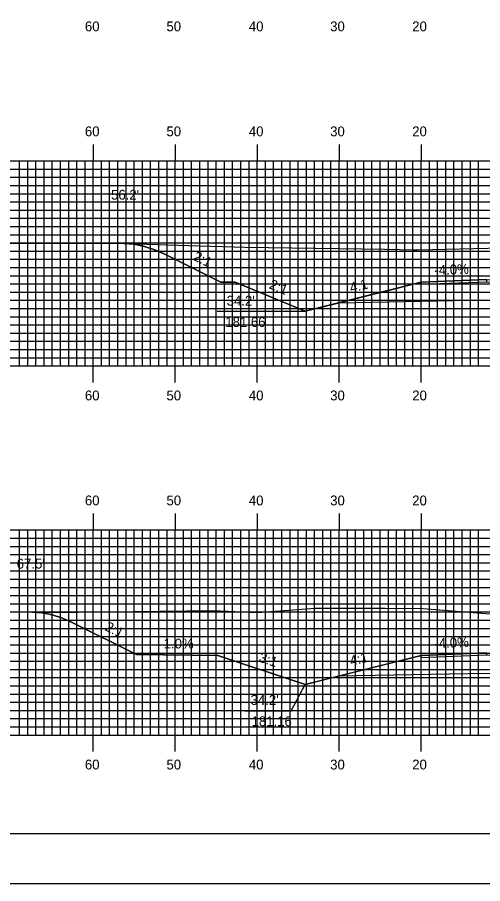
# Model space of a CAD drawing. Extents: x 1797601 to 1797944, y 442591 to 442811.
# Drawn here: x 1797697.2 to 1797753.9, y 442590.5 to 442696.2 of the extents above; entities that cross this region are included whole.
import ezdxf

# ---------------------------------------------------------------- set-up
doc = ezdxf.new("R2010")
doc.units = 0
for name, color, linetype in [('ANNOTATION', 7, 'Continuous'), ('BORDER', 7, 'Continuous'), ('D_Roadway_Centerline', 7, 'Continuous'), ('D_Roadway_Edge_Shoulder', 7, 'Continuous'), ('D_Roadway_SlopeLines', 7, 'Continuous'), ('D_Roadway_SubGrade', 7, 'Continuous'), ('D_Text_Standard', 7, 'Continuous'), ('H_V ANNOTATION', 7, 'Continuous'), ('MAJOR', 7, 'Continuous'), ('MINOR', 7, 'Continuous'), ('PDRAIN', 7, 'Continuous'), ('PLOT BOUNDARY', 7, 'Continuous'), ('S_Roadway_Centerline', 7, 'Continuous')]:
    doc.layers.add(name, color=color, linetype=linetype)

msp = doc.modelspace()

# ---------------------------------------------------------------- linework, layer by layer
at = {"layer": 'ANNOTATION'}
msp.add_lwpolyline([(1797724.9, 442611.62), (1797730.59, 442611.62), (1797732.27, 442614.83)], dxfattribs=at)
at = {"layer": 'BORDER'}
msp.add_lwpolyline([(1797616.84, 442596.67), (1797936.84, 442596.67), (1797936.84, 442806.67), (1797616.84, 442806.67)], close=True, dxfattribs=at)
at = {"layer": 'D_Roadway_Centerline'}
for points in [[(1797710.19, 442668.6), (1797711.44, 442668.5), (1797712.69, 442668.24), (1797713.94, 442667.84), (1797715.19, 442667.28), (1797721.99, 442663.89), (1797723.77, 442663.87), (1797732.27, 442660.33), (1797736.27, 442661.33), (1797746.44, 442663.87), (1797754.44, 442664.19), (1797766.44, 442663.95), (1797778.44, 442663.71), (1797786.44, 442663.39), (1797796.62, 442660.85), (1797800.62, 442659.85), (1797809.12, 442663.39), (1797813.34, 442663.43), (1797817.69, 442665.61), (1797818.94, 442666.15), (1797820.19, 442666.52), (1797821.44, 442666.73), (1797822.69, 442666.77)], [(1797698.94, 442623.65), (1797700.19, 442623.55), (1797701.44, 442623.31), (1797702.69, 442622.91), (1797703.94, 442622.36), (1797711.73, 442618.47), (1797721.64, 442618.37), (1797732.27, 442614.83), (1797736.27, 442615.83), (1797746.44, 442618.37), (1797754.44, 442618.69), (1797766.44, 442618.45), (1797778.44, 442618.21), (1797786.44, 442617.89), (1797796.62, 442615.35), (1797800.62, 442614.35), (1797811.25, 442617.89), (1797823.86, 442618.01), (1797828.94, 442620.56), (1797830.19, 442621.1), (1797831.44, 442621.48), (1797832.69, 442621.7), (1797833.94, 442621.75)]]:
    msp.add_lwpolyline(points, dxfattribs=at)
at = {"layer": 'D_Roadway_Edge_Shoulder'}
for points in [[(1797754.44, 442664.19), (1797746.44, 442663.87), (1797746.44, 442663.62), (1797754.44, 442663.94)], [(1797754.44, 442618.69), (1797746.44, 442618.37), (1797746.44, 442618.12), (1797754.44, 442618.44)]]:
    msp.add_lwpolyline(points, close=True, dxfattribs=at)
at = {"layer": 'D_Roadway_SlopeLines'}
for points in [[(1797723.77, 442663.87), (1797721.99, 442663.89), (1797715.19, 442667.28), (1797713.94, 442667.84), (1797712.69, 442668.24), (1797711.44, 442668.5), (1797710.19, 442668.6)], [(1797732.27, 442660.33), (1797723.77, 442663.87)], [(1797746.44, 442663.87), (1797732.27, 442660.33)], [(1797721.64, 442618.37), (1797711.73, 442618.47), (1797703.94, 442622.36), (1797702.69, 442622.91), (1797701.44, 442623.31), (1797700.19, 442623.55), (1797698.94, 442623.65)], [(1797732.27, 442614.83), (1797721.64, 442618.37)], [(1797746.44, 442618.37), (1797732.27, 442614.83)]]:
    msp.add_lwpolyline(points, dxfattribs=at)
at = {"layer": 'D_Roadway_SubGrade'}
for points in [[(1797754.44, 442661.69), (1797736.27, 442661.33), (1797746.44, 442663.87), (1797746.44, 442663.62), (1797754.44, 442663.94), (1797766.44, 442663.7), (1797778.44, 442663.46), (1797786.44, 442663.14), (1797786.44, 442663.39), (1797796.62, 442660.85), (1797778.44, 442661.21), (1797766.44, 442661.45)], [(1797754.44, 442616.19), (1797736.27, 442615.83), (1797746.44, 442618.37), (1797746.44, 442618.12), (1797754.44, 442618.44), (1797766.44, 442618.2), (1797778.44, 442617.96), (1797786.44, 442617.64), (1797786.44, 442617.89), (1797796.62, 442615.35), (1797778.44, 442615.71), (1797766.44, 442615.95)]]:
    msp.add_lwpolyline(points, close=True, dxfattribs=at)
at = {"layer": 'MAJOR'}
for p, q in [((1797706.44, 442680.67), (1797706.44, 442678.67)), ((1797716.44, 442680.67), (1797716.44, 442678.67)), ((1797726.44, 442680.67), (1797726.44, 442678.67)), ((1797736.44, 442680.67), (1797736.44, 442678.67)), ((1797746.44, 442680.67), (1797746.44, 442678.67)), ((1797626.44, 442678.67), (1797906.44, 442678.67)), ((1797626.44, 442678.67), (1797906.44, 442678.67)), ((1797706.44, 442653.67), (1797706.44, 442678.67)), ((1797716.44, 442653.67), (1797716.44, 442678.67)), ((1797726.44, 442653.67), (1797726.44, 442678.67)), ((1797736.44, 442653.67), (1797736.44, 442678.67)), ((1797746.44, 442653.67), (1797746.44, 442678.67)), ((1797626.44, 442673.67), (1797906.44, 442673.67)), ((1797626.44, 442668.67), (1797906.44, 442668.67)), ((1797626.44, 442663.67), (1797906.44, 442663.67)), ((1797626.44, 442658.67), (1797906.44, 442658.67)), ((1797626.44, 442653.67), (1797906.44, 442653.67)), ((1797626.44, 442653.67), (1797906.44, 442653.67)), ((1797706.44, 442651.66), (1797706.44, 442653.67)), ((1797716.44, 442651.66), (1797716.44, 442653.67)), ((1797726.44, 442651.66), (1797726.44, 442653.67)), ((1797736.44, 442651.66), (1797736.44, 442653.67)), ((1797746.44, 442651.66), (1797746.44, 442653.67)), ((1797706.44, 442635.67), (1797706.44, 442633.67)), ((1797716.44, 442635.67), (1797716.44, 442633.67)), ((1797726.44, 442635.67), (1797726.44, 442633.67)), ((1797736.44, 442635.67), (1797736.44, 442633.67)), ((1797746.44, 442635.67), (1797746.44, 442633.67)), ((1797626.44, 442633.67), (1797906.44, 442633.67)), ((1797626.44, 442633.67), (1797906.44, 442633.67)), ((1797706.44, 442608.67), (1797706.44, 442633.67)), ((1797716.44, 442608.67), (1797716.44, 442633.67)), ((1797726.44, 442608.67), (1797726.44, 442633.67)), ((1797736.44, 442608.67), (1797736.44, 442633.67)), ((1797746.44, 442608.67), (1797746.44, 442633.67)), ((1797626.44, 442628.67), (1797906.44, 442628.67)), ((1797626.44, 442623.67), (1797906.44, 442623.67)), ((1797626.44, 442618.67), (1797906.44, 442618.67)), ((1797626.44, 442613.67), (1797906.44, 442613.67)), ((1797626.44, 442608.67), (1797906.44, 442608.67)), ((1797626.44, 442608.67), (1797906.44, 442608.67)), ((1797706.44, 442606.66), (1797706.44, 442608.67)), ((1797716.44, 442606.66), (1797716.44, 442608.67)), ((1797726.44, 442606.66), (1797726.44, 442608.67)), ((1797736.44, 442606.66), (1797736.44, 442608.67)), ((1797746.44, 442606.66), (1797746.44, 442608.67))]:
    msp.add_line(p, q, dxfattribs=at)
at = {"layer": 'MINOR'}
for p, q in [((1797697.44, 442653.67), (1797697.44, 442678.67)), ((1797698.44, 442653.67), (1797698.44, 442678.67)), ((1797699.44, 442653.67), (1797699.44, 442678.67)), ((1797700.44, 442653.67), (1797700.44, 442678.67)), ((1797701.44, 442653.67), (1797701.44, 442678.67)), ((1797702.44, 442653.67), (1797702.44, 442678.67)), ((1797703.44, 442653.67), (1797703.44, 442678.67)), ((1797704.44, 442653.67), (1797704.44, 442678.67)), ((1797705.44, 442653.67), (1797705.44, 442678.67)), ((1797707.44, 442653.67), (1797707.44, 442678.67)), ((1797708.44, 442653.67), (1797708.44, 442678.67)), ((1797709.44, 442653.67), (1797709.44, 442678.67)), ((1797710.44, 442653.67), (1797710.44, 442678.67)), ((1797711.44, 442653.67), (1797711.44, 442678.67)), ((1797712.44, 442653.67), (1797712.44, 442678.67)), ((1797713.44, 442653.67), (1797713.44, 442678.67)), ((1797714.44, 442653.67), (1797714.44, 442678.67)), ((1797715.44, 442653.67), (1797715.44, 442678.67)), ((1797717.44, 442653.67), (1797717.44, 442678.67)), ((1797718.44, 442653.67), (1797718.44, 442678.67)), ((1797719.44, 442653.67), (1797719.44, 442678.67)), ((1797720.44, 442653.67), (1797720.44, 442678.67)), ((1797721.44, 442653.67), (1797721.44, 442678.67)), ((1797722.44, 442653.67), (1797722.44, 442678.67)), ((1797723.44, 442653.67), (1797723.44, 442678.67)), ((1797724.44, 442653.67), (1797724.44, 442678.67)), ((1797725.44, 442653.67), (1797725.44, 442678.67)), ((1797727.44, 442653.67), (1797727.44, 442678.67)), ((1797728.44, 442653.67), (1797728.44, 442678.67)), ((1797729.44, 442653.67), (1797729.44, 442678.67)), ((1797730.44, 442653.67), (1797730.44, 442678.67)), ((1797731.44, 442653.67), (1797731.44, 442678.67)), ((1797732.44, 442653.67), (1797732.44, 442678.67)), ((1797733.44, 442653.67), (1797733.44, 442678.67)), ((1797734.44, 442653.67), (1797734.44, 442678.67)), ((1797735.44, 442653.67), (1797735.44, 442678.67)), ((1797737.44, 442653.67), (1797737.44, 442678.67)), ((1797738.44, 442653.67), (1797738.44, 442678.67)), ((1797739.44, 442653.67), (1797739.44, 442678.67)), ((1797740.44, 442653.67), (1797740.44, 442678.67)), ((1797741.44, 442653.67), (1797741.44, 442678.67)), ((1797742.44, 442653.67), (1797742.44, 442678.67)), ((1797743.44, 442653.67), (1797743.44, 442678.67)), ((1797744.44, 442653.67), (1797744.44, 442678.67)), ((1797745.44, 442653.67), (1797745.44, 442678.67)), ((1797747.44, 442653.67), (1797747.44, 442678.67)), ((1797748.44, 442653.67), (1797748.44, 442678.67)), ((1797749.44, 442653.67), (1797749.44, 442678.67)), ((1797750.44, 442653.67), (1797750.44, 442678.67)), ((1797751.44, 442653.67), (1797751.44, 442678.67)), ((1797752.44, 442653.67), (1797752.44, 442678.67)), ((1797753.44, 442653.67), (1797753.44, 442678.67)), ((1797626.44, 442677.67), (1797906.44, 442677.67)), ((1797626.44, 442676.67), (1797906.44, 442676.67)), ((1797626.44, 442675.67), (1797906.44, 442675.67)), ((1797626.44, 442674.67), (1797906.44, 442674.67)), ((1797626.44, 442672.67), (1797906.44, 442672.67)), ((1797626.44, 442671.67), (1797906.44, 442671.67)), ((1797626.44, 442670.67), (1797906.44, 442670.67)), ((1797626.44, 442669.67), (1797906.44, 442669.67)), ((1797626.44, 442667.67), (1797906.44, 442667.67)), ((1797626.44, 442666.67), (1797906.44, 442666.67)), ((1797626.44, 442665.67), (1797906.44, 442665.67)), ((1797626.44, 442664.67), (1797906.44, 442664.67)), ((1797626.44, 442662.67), (1797906.44, 442662.67)), ((1797626.44, 442661.67), (1797906.44, 442661.67)), ((1797626.44, 442660.67), (1797906.44, 442660.67)), ((1797626.44, 442659.67), (1797906.44, 442659.67)), ((1797626.44, 442657.67), (1797906.44, 442657.67)), ((1797626.44, 442656.67), (1797906.44, 442656.67)), ((1797626.44, 442655.67), (1797906.44, 442655.67)), ((1797626.44, 442654.67), (1797906.44, 442654.67)), ((1797697.44, 442608.67), (1797697.44, 442633.67)), ((1797698.44, 442608.67), (1797698.44, 442633.67)), ((1797699.44, 442608.67), (1797699.44, 442633.67)), ((1797700.44, 442608.67), (1797700.44, 442633.67)), ((1797701.44, 442608.67), (1797701.44, 442633.67)), ((1797702.44, 442608.67), (1797702.44, 442633.67)), ((1797703.44, 442608.67), (1797703.44, 442633.67)), ((1797704.44, 442608.67), (1797704.44, 442633.67)), ((1797705.44, 442608.67), (1797705.44, 442633.67)), ((1797707.44, 442608.67), (1797707.44, 442633.67)), ((1797708.44, 442608.67), (1797708.44, 442633.67)), ((1797709.44, 442608.67), (1797709.44, 442633.67)), ((1797710.44, 442608.67), (1797710.44, 442633.67)), ((1797711.44, 442608.67), (1797711.44, 442633.67)), ((1797712.44, 442608.67), (1797712.44, 442633.67)), ((1797713.44, 442608.67), (1797713.44, 442633.67)), ((1797714.44, 442608.67), (1797714.44, 442633.67)), ((1797715.44, 442608.67), (1797715.44, 442633.67)), ((1797717.44, 442608.67), (1797717.44, 442633.67)), ((1797718.44, 442608.67), (1797718.44, 442633.67)), ((1797719.44, 442608.67), (1797719.44, 442633.67)), ((1797720.44, 442608.67), (1797720.44, 442633.67)), ((1797721.44, 442608.67), (1797721.44, 442633.67)), ((1797722.44, 442608.67), (1797722.44, 442633.67)), ((1797723.44, 442608.67), (1797723.44, 442633.67)), ((1797724.44, 442608.67), (1797724.44, 442633.67)), ((1797725.44, 442608.67), (1797725.44, 442633.67)), ((1797727.44, 442608.67), (1797727.44, 442633.67)), ((1797728.44, 442608.67), (1797728.44, 442633.67)), ((1797729.44, 442608.67), (1797729.44, 442633.67)), ((1797730.44, 442608.67), (1797730.44, 442633.67)), ((1797731.44, 442608.67), (1797731.44, 442633.67)), ((1797732.44, 442608.67), (1797732.44, 442633.67)), ((1797733.44, 442608.67), (1797733.44, 442633.67)), ((1797734.44, 442608.67), (1797734.44, 442633.67)), ((1797735.44, 442608.67), (1797735.44, 442633.67)), ((1797737.44, 442608.67), (1797737.44, 442633.67)), ((1797738.44, 442608.67), (1797738.44, 442633.67)), ((1797739.44, 442608.67), (1797739.44, 442633.67)), ((1797740.44, 442608.67), (1797740.44, 442633.67)), ((1797741.44, 442608.67), (1797741.44, 442633.67)), ((1797742.44, 442608.67), (1797742.44, 442633.67)), ((1797743.44, 442608.67), (1797743.44, 442633.67)), ((1797744.44, 442608.67), (1797744.44, 442633.67)), ((1797745.44, 442608.67), (1797745.44, 442633.67)), ((1797747.44, 442608.67), (1797747.44, 442633.67)), ((1797748.44, 442608.67), (1797748.44, 442633.67)), ((1797749.44, 442608.67), (1797749.44, 442633.67)), ((1797750.44, 442608.67), (1797750.44, 442633.67)), ((1797751.44, 442608.67), (1797751.44, 442633.67)), ((1797752.44, 442608.67), (1797752.44, 442633.67)), ((1797753.44, 442608.67), (1797753.44, 442633.67)), ((1797626.44, 442632.67), (1797906.44, 442632.67)), ((1797626.44, 442631.67), (1797906.44, 442631.67)), ((1797626.44, 442630.67), (1797906.44, 442630.67)), ((1797626.44, 442629.67), (1797906.44, 442629.67)), ((1797626.44, 442627.67), (1797906.44, 442627.67)), ((1797626.44, 442626.67), (1797906.44, 442626.67)), ((1797626.44, 442625.67), (1797906.44, 442625.67)), ((1797626.44, 442624.67), (1797906.44, 442624.67)), ((1797626.44, 442622.67), (1797906.44, 442622.67)), ((1797626.44, 442621.67), (1797906.44, 442621.67)), ((1797626.44, 442620.67), (1797906.44, 442620.67)), ((1797626.44, 442619.67), (1797906.44, 442619.67)), ((1797626.44, 442617.67), (1797906.44, 442617.67)), ((1797626.44, 442616.67), (1797906.44, 442616.67)), ((1797626.44, 442615.67), (1797906.44, 442615.67)), ((1797626.44, 442614.67), (1797906.44, 442614.67)), ((1797626.44, 442612.67), (1797906.44, 442612.67)), ((1797626.44, 442611.67), (1797906.44, 442611.67)), ((1797626.44, 442610.67), (1797906.44, 442610.67)), ((1797626.44, 442609.67), (1797906.44, 442609.67))]:
    msp.add_line(p, q, dxfattribs=at)
at = {"layer": 'PDRAIN'}
msp.add_line((1797721.55, 442660.33), (1797732.27, 442660.33), dxfattribs=at)
at = {"layer": 'PLOT BOUNDARY'}
msp.add_lwpolyline([(1797600.66, 442590.55), (1797940.66, 442590.55), (1797940.66, 442810.55), (1797600.66, 442810.55)], close=True, dxfattribs=at)
at = {"layer": 'S_Roadway_Centerline'}
for points in [[(1797692.6, 442668.6), (1797703.82, 442668.64), (1797710.4, 442668.6), (1797719.38, 442668.33), (1797724.97, 442668.13), (1797742.03, 442667.89), (1797745.51, 442667.83), (1797746.07, 442667.84), (1797756.3, 442668.06), (1797765.54, 442667.52), (1797767.98, 442667.4), (1797770.93, 442667.39), (1797787, 442667.37), (1797791.84, 442667.4), (1797798.61, 442667.13), (1797808.08, 442667.03), (1797815.1, 442667.03), (1797826.56, 442666.64)], [(1797692.59, 442623.76), (1797701.04, 442623.61), (1797708.19, 442623.68), (1797721.04, 442623.87), (1797726.49, 442623.62), (1797733.52, 442624.15), (1797739.54, 442624.14), (1797742.04, 442624.15), (1797746.65, 442624.1), (1797754.31, 442623.48), (1797761.56, 442623.32), (1797762.84, 442623.24), (1797767.77, 442623.12), (1797783.91, 442622.58), (1797785.81, 442622.61), (1797788.16, 442622.56), (1797797.92, 442622.17), (1797805.46, 442621.94), (1797815.49, 442621.88), (1797824.93, 442621.95)]]:
    msp.add_lwpolyline(points, dxfattribs=at)

# ---------------------------------------------------------------- texts
at = {"layer": 'ANNOTATION'}
for s, rotation, p in [('2:1', 333.4349, (1797718.53, 442666.65)), ('-4.0%', 2.2906, (1797748.08, 442664.74)), ('2:1', 337.3801, (1797727.8, 442663.16)), ('4:1', 14.0362, (1797737.89, 442662.59)), ('2:1', 333.4349, (1797707.77, 442621.48)), ('1.0%', 359.4271, (1797715.02, 442619.24)), ('-4.0%', 2.2906, (1797748.08, 442619.24)), ('3:1', 341.5651, (1797726.56, 442617.64)), ('4:1', 14.0362, (1797737.89, 442617.09))]:
    msp.add_text(s, height=1.2, rotation=rotation, dxfattribs=at).set_placement(p)
for s, p in [("34.2'", (1797722.71, 442661.02)), ('181.66', (1797722.54, 442658.42)), ("34.2'", (1797725.63, 442612.35)), ('181.16', (1797725.75, 442609.75))]:
    msp.add_text(s, height=1.2, dxfattribs=at).set_placement(p)
at = {"layer": 'D_Text_Standard'}
for s, p in [("56.2'", (1797708.61, 442673.94)), ("67.5'", (1797697.1, 442628.96))]:
    msp.add_text(s, height=1.2, dxfattribs=at).set_placement(p)
at = {"layer": 'H_V ANNOTATION'}
for s, p in [('60', (1797705.42, 442694.47)), ('50', (1797715.37, 442694.47)), ('40', (1797725.42, 442694.47)), ('30', (1797735.34, 442694.47)), ('20', (1797745.35, 442694.47)), ('60', (1797705.42, 442681.67)), ('50', (1797715.37, 442681.67)), ('40', (1797725.42, 442681.67)), ('30', (1797735.34, 442681.67)), ('20', (1797745.35, 442681.67)), ('60', (1797705.42, 442649.47)), ('50', (1797715.37, 442649.47)), ('40', (1797725.42, 442649.47)), ('30', (1797735.34, 442649.47)), ('20', (1797745.35, 442649.47)), ('60', (1797705.42, 442636.67)), ('50', (1797715.37, 442636.67)), ('40', (1797725.42, 442636.67)), ('30', (1797735.34, 442636.67)), ('20', (1797745.35, 442636.67)), ('60', (1797705.42, 442604.47)), ('50', (1797715.37, 442604.47)), ('40', (1797725.42, 442604.47)), ('30', (1797735.34, 442604.47)), ('20', (1797745.35, 442604.47))]:
    msp.add_text(s, height=1.2, dxfattribs=at).set_placement(p)

doc.saveas('drawing.dxf')
